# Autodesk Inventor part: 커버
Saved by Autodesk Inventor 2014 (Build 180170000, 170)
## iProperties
Created: 2025-02
Part Number: 커버
Material: 알루미늄 6061
Document SubType Name: Modeling
Designer: dg
Density: 2.71 g/cm^3
Appearance: 알루미늄 - 평지
Mass: 271.543 g
Surface Area: 388.646 cm^2
Volume: 100.2 cm^3
Author: jhkim
Creation Date: 2025-01-06
Sending System: Autodesk Inventor 2025
Preprocessor: ST-DEVELOPER v20
Author: dg
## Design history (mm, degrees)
node "커버1"
node "솔리드1"
node "기준1"
